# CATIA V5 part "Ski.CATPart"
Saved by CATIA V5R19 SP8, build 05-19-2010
Part number: Ski
Material "Aucun"
Bounding box of the stored display mesh (mm): x 0 to 100, y -1568.817 to 491.036, z 0 to 57.287
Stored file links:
  G:\EU_thinkMotion\CFAO_2010\MMS_groupe2\MMS_groupe2\A reprendre\rbouchet\rbouchet_Catia\Ski.CATPart
  C:\Program Files\Dassault Systemes\B19\intel_a\startup\materials\French\Catalog.CATMaterial
  G:\EU_thinkMotion\CFAO_2010\MMS_groupe2\MMS_groupe2\A reprendre\rbouchet\rbouchet_Catia\Assemblage complet.CATProduct
  G:\EU_thinkMotion\CFAO_2010\MMS_groupe2\MMS_groupe2\A reprendre\rbouchet\rbouchet_Catia\Glissiere.CATPart
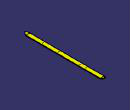
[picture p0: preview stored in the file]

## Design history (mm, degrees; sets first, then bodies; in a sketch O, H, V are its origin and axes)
Set1
  DatumCurve1 to DatumCurve4: linked copy from another document
Body1 (main body), material "Aucun"
  Sketch1 on yz-plane, origin (0, 0, 0), H (0, 1, 0), V (0, 0, 1)
    line L1 (-1496.8213, 0) -> (403.1787, 0)
    point P1 (-1496.8213, 0)
    point P2 (403.1787, 0)
    arc A1 centre (403.1787, 105) radius 105 from (403.1787, 0) to (489.7543, 45.589) ccw
    point P3 (403.1787, 105)
    arc A2 centre (483.5703, 49.8326) radius 7.5 from (489.7543, 45.589) to (477.3863, 54.0763) ccw
    point P6 (477.3863, 54.0763)
    arc A3 centre (403.1787, 105) radius 90 from (403.1787, 15) to (477.3863, 54.0763) ccw
    point P7 (403.1787, 105)
    point P8 (477.3863, 54.0763)
    point P9 (403.1787, 15)
    line L2 (403.1787, 15) -> (-1496.8213, 15)
    arc A4 centre (-1496.8213, 105) radius 105 from (-1567.5308, 27.378) to (-1496.8213, 0) ccw
    point P12 (-1567.5308, 27.378)
    arc A5 centre (-1496.8213, 105) radius 90 from (-1557.4294, 38.4668) to (-1496.8213, 15) ccw
    point P13 (-1557.4294, 38.4668)
    arc A6 centre (-1562.4801, 32.9224) radius 7.5 from (-1557.4294, 38.4668) to (-1567.5308, 27.378) ccw
    point P15 (-1557.4294, 38.4668)
    point P16 (-1567.5308, 27.378)
    length L2 = 1900
    distance L2 L1 = 15
    distance P9 P2 = 15.0001
    radius A3 = 90
    radius A5 = 90
    coincidence: P1 H, P8 A2, P8 P6, P3 P7, P15 A5, P16 A4, P16 P12, P15 P13
    horizontal: L1 H, L2 H
    tangency: A1 L1, A3 A2, A1 A2, A4 L1, A5 L2, A6 A5, A4 A6
  Pad1: profile Sketch1, direction (1, 0, 0), length 100
  Sketch2 on face of Pad1 from Sketch1.L2, origin (0, 0, 15), H (1, 0, 0), V (0, 1, 0)
    spline S1 through (0, 402.4979) (50, 493.1787) (100, 402.4979)
    reference projected line E1 (0, 253.1787) -> (0, 339.7543) from edge [start face of Pad1 | face of Pad1 from Sketch1.A1]
    reference projected line E2 (0, 403.1787) -> (100, 403.1787) from edge [face of Pad1 from Sketch1.L2 | face of Pad1 from Sketch1.A3]
    reference projected line E3 (100, 403.1787) -> (100, -1496.8213) from edge [face of Pad1 from Sketch1.L2 | end face of Pad1]
    point P1 (0, 402.4979)
    point P2 (50, 493.1787)
    point P3 (100, 402.4979)
    distance P2 E1 = 50
    distance P2 E2 = 90
    distance P1 P3 = 100
    coincidence: P1 V, P3 E3
  Pocket1: profile Sketch2, direction (0, 0, 1), length 100, mirrored extent
  Sketch3 on face of Pad1 from Sketch1.L2, origin (0, 0, 15), H (1, 0, 0), V (0, 1, 0)
    spline S1 through (0, -1496.8213) (50, -1568.8213) (100, -1496.8213)
    reference projected point E1 (100, -1496.8213) from vertex [face of Pad1 from Sketch1.A5 | end face of Pad1 | face of Pad1 from Sketch1.L2]
    reference projected point E2 (0, -1496.8213) from vertex [face of Pad1 from Sketch1.A5 | start face of Pad1 | face of Pad1 from Sketch1.L2]
    reference projected line E3 (0, 253.1787) -> (0, -1496.8213) from edge [start face of Pad1 | face of Pad1 from Sketch1.L2]
    reference projected line E4 (0, -1496.8213) -> (100, -1496.8213) from edge [face of Pad1 from Sketch1.A5 | face of Pad1 from Sketch1.L2]
    point P1 (0, -1496.8213)
    point P2 (100, -1496.8213)
    point P3 (50, -1568.8213)
    distance P3 E3 = 50
    distance P3 E4 = 72
    coincidence: P1 V, P2 E1, P1 E2
  Pocket2: profile Sketch3, direction (0, 0, -1), length 100, mirrored extent
  Sketch4 on face of Pad1 from Sketch1.L2, origin (0, 0, 15), H (1, 0, 0), V (0, 1, 0)
    circle A1 centre (38.7911, -160.427) radius 3
    reference projected circle E1 centre (38.7911, -160.427) radius 3 from edge of DatumCurve1
    radius A1 = 3
    distance A1 E1 = 0
  Pocket3: profile Sketch4, direction (0, 0, -1), length 7
  RectPattern1: of Pocket3, direction 1 instances 2, spacing 22.5, along edge of DatumCurve2 reversed, direction 2 instances 2, spacing 550, along edge of DatumCurve3
  Sketch5 on face of Pad1 from Sketch1.L2, origin (0, 0, 15), H (1, 0, 0), V (0, 1, 0)
    circle A1 centre (57.0047, -12.4697) radius 3
    reference projected circle E1 centre (57.0047, -12.4697) radius 3 from edge of DatumCurve4
    radius A1 = 3
    distance A1 E1 = 0
  Pocket4: profile Sketch5, direction (0, 0, -1), length 7
  RectPattern2: of Pocket4, direction 1 instances 2, spacing 14, along edge of DatumCurve2, direction 2 instances 2, spacing 1100, along edge of DatumCurve3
